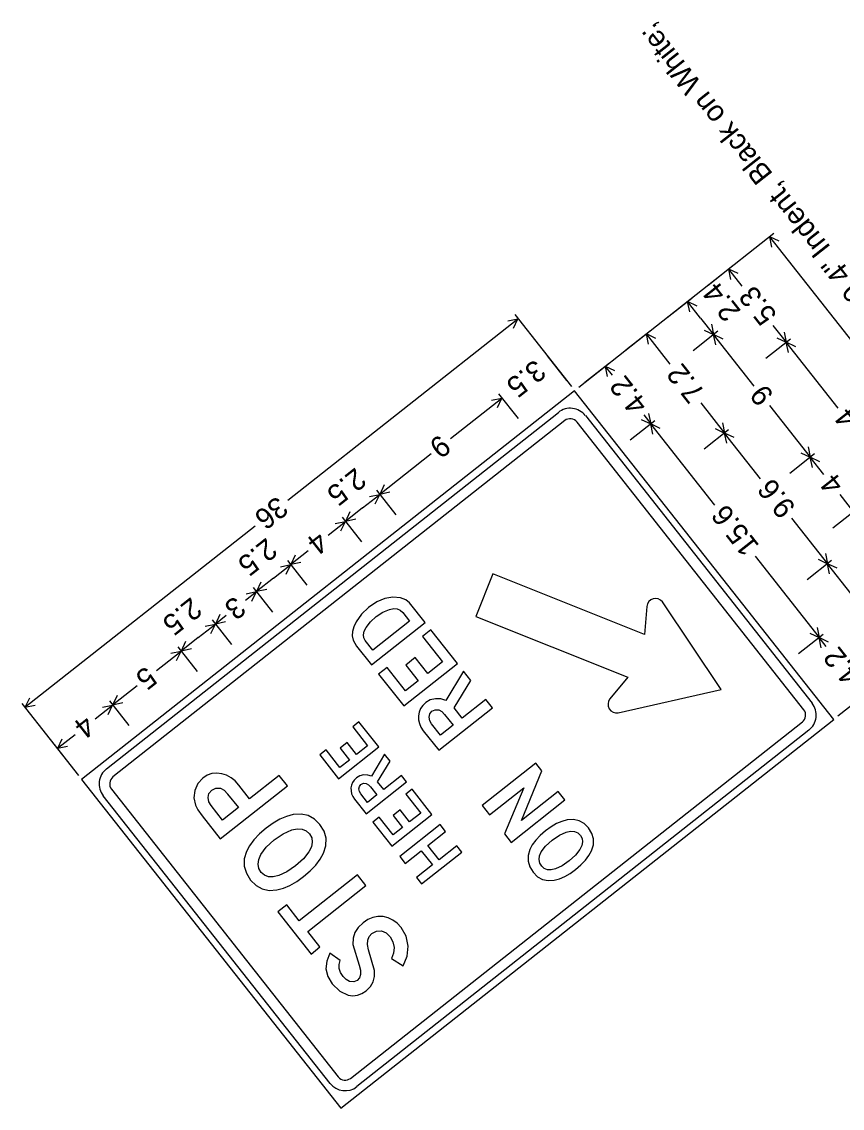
# Model space of a CAD drawing. Extents: x 672239 to 673995, y 1673540 to 1675195.
# Drawn here: x 672602.49 to 672638.35, y 1674789.09 to 1674836.55 of the extents above; entities that cross this region are included whole.
import ezdxf

# ---------------------------------------------------------------- set-up
doc = ezdxf.new("R2010")
doc.units = 0
doc.layers.add('C-ALGN-LINE', color=7, linetype='Continuous')

msp = doc.modelspace()

# ---------------------------------------------------------------- linework, layer by layer
at = {"layer": 'C-ALGN-LINE'}
for p, q in [((672635.358, 1674827.298), (672626.831, 1674820.575)), ((672640.275, 1674820.692), (672635.179, 1674827.156)), ((672635.593, 1674826.961), (672635.179, 1674827.156)), ((672635.272, 1674826.708), (672635.179, 1674827.156)), ((672633.563, 1674825.882), (672632.486, 1674825.033)), ((672633.968, 1674825), (672633.384, 1674825.741)), ((672633.797, 1674825.546), (672633.384, 1674825.741)), ((672633.476, 1674825.293), (672633.384, 1674825.741)), ((672631.768, 1674824.467), (672630.691, 1674823.618)), ((672632.156, 1674823.605), (672631.588, 1674824.326)), ((672632.002, 1674824.131), (672631.588, 1674824.326)), ((672631.681, 1674823.878), (672631.588, 1674824.326)), ((672624.033, 1674823.755), (672626.51, 1674820.613)), ((672614.118, 1674815.648), (672624.175, 1674823.575)), ((672623.727, 1674823.482), (672624.175, 1674823.575)), ((672623.98, 1674823.162), (672624.175, 1674823.575)), ((672632.156, 1674823.605), (672632.725, 1674822.884)), ((672632.632, 1674823.332), (672632.725, 1674822.884)), ((672635.318, 1674823.287), (672635.902, 1674822.546)), ((672629.973, 1674823.052), (672628.895, 1674822.203)), ((672630.83, 1674821.596), (672629.793, 1674822.91)), ((672630.207, 1674822.716), (672629.793, 1674822.91)), ((672629.886, 1674822.463), (672629.793, 1674822.91)), ((672632.904, 1674823.026), (672631.827, 1674822.176)), ((672632.904, 1674823.026), (672631.827, 1674822.176)), ((672632.311, 1674823.079), (672632.725, 1674822.884)), ((672634.502, 1674820.629), (672632.725, 1674822.884)), ((672633.138, 1674822.69), (672632.725, 1674822.884)), ((672632.817, 1674822.437), (672632.725, 1674822.884)), ((672636.082, 1674822.688), (672635.005, 1674821.838)), ((672636.082, 1674822.688), (672635.005, 1674821.838)), ((672635.488, 1674822.741), (672635.902, 1674822.546)), ((672635.809, 1674822.994), (672635.902, 1674822.546)), ((672638.171, 1674819.668), (672635.902, 1674822.546)), ((672636.316, 1674822.351), (672635.902, 1674822.546)), ((672635.995, 1674822.098), (672635.902, 1674822.546)), ((672625.448, 1674821.96), (672626.298, 1674820.883)), ((672628.177, 1674821.637), (672627.1, 1674820.788)), ((672628.306, 1674821.104), (672627.998, 1674821.495)), ((672628.412, 1674821.3), (672627.998, 1674821.495)), ((672628.091, 1674821.047), (672627.998, 1674821.495)), ((672621.226, 1674818.34), (672623.472, 1674820.111)), ((672623.024, 1674820.018), (672623.472, 1674820.111)), ((672623.277, 1674819.697), (672623.472, 1674820.111)), ((672623.331, 1674820.29), (672624.18, 1674819.213)), ((672623.331, 1674820.29), (672624.18, 1674819.213)), ((672632.167, 1674819.899), (672633.204, 1674818.584)), ((672629.671, 1674819.373), (672629.979, 1674818.982)), ((672629.886, 1674819.43), (672629.979, 1674818.982)), ((672635.171, 1674819.781), (672636.948, 1674817.527)), ((672630.159, 1674819.123), (672629.082, 1674818.274)), ((672630.159, 1674819.123), (672629.082, 1674818.274)), ((672629.566, 1674819.177), (672629.979, 1674818.982)), ((672632.781, 1674815.428), (672629.979, 1674818.982)), ((672630.393, 1674818.787), (672629.979, 1674818.982)), ((672630.072, 1674818.534), (672629.979, 1674818.982)), ((672633.111, 1674819.032), (672633.204, 1674818.584)), ((672633.383, 1674818.725), (672632.306, 1674817.876)), ((672633.383, 1674818.725), (672632.306, 1674817.876)), ((672632.79, 1674818.779), (672633.204, 1674818.584)), ((672634.776, 1674816.589), (672633.204, 1674818.584)), ((672633.618, 1674818.389), (672633.204, 1674818.584)), ((672633.297, 1674818.136), (672633.204, 1674818.584)), ((672636.856, 1674817.974), (672636.948, 1674817.527)), ((672620.379, 1674817.672), (672618.133, 1674815.902)), ((672637.128, 1674817.668), (672636.051, 1674816.819)), ((672636.535, 1674817.721), (672636.948, 1674817.527)), ((672637.548, 1674816.767), (672636.948, 1674817.527)), ((672637.362, 1674817.332), (672636.948, 1674817.527)), ((672637.041, 1674817.079), (672636.948, 1674817.527)), ((672617.992, 1674816.081), (672618.841, 1674815.004)), ((672618.328, 1674816.315), (672618.133, 1674815.902)), ((672617.385, 1674815.312), (672618.133, 1674815.902)), ((672617.685, 1674815.809), (672618.133, 1674815.902)), ((672617.938, 1674815.488), (672618.133, 1674815.902)), ((672618.581, 1674815.995), (672618.133, 1674815.902)), ((672638.237, 1674815.892), (672638.835, 1674815.133)), ((672617.385, 1674815.312), (672616.637, 1674814.722)), ((672616.832, 1674815.136), (672616.637, 1674814.722)), ((672639.015, 1674815.274), (672637.938, 1674814.425)), ((672615.877, 1674814.123), (672616.637, 1674814.722)), ((672616.189, 1674814.629), (672616.637, 1674814.722)), ((672616.442, 1674814.308), (672616.637, 1674814.722)), ((672616.496, 1674814.902), (672617.345, 1674813.825)), ((672617.085, 1674814.815), (672616.637, 1674814.722)), ((672636.132, 1674814.87), (672637.704, 1674812.875)), ((672612.688, 1674814.52), (672602.632, 1674806.592)), ((672615.004, 1674813.434), (672614.244, 1674812.835)), ((672614.439, 1674813.249), (672614.244, 1674812.835)), ((672634.537, 1674813.201), (672637.339, 1674809.647)), ((672637.611, 1674813.323), (672637.704, 1674812.875)), ((672613.496, 1674812.245), (672614.244, 1674812.835)), ((672613.796, 1674812.742), (672614.244, 1674812.835)), ((672614.049, 1674812.421), (672614.244, 1674812.835)), ((672614.102, 1674813.015), (672614.951, 1674811.938)), ((672614.691, 1674812.928), (672614.244, 1674812.835)), ((672637.884, 1674813.017), (672636.807, 1674812.168)), ((672637.291, 1674813.07), (672637.704, 1674812.875)), ((672638.741, 1674811.56), (672637.704, 1674812.875)), ((672638.118, 1674812.68), (672637.704, 1674812.875)), ((672637.797, 1674812.427), (672637.704, 1674812.875)), ((672646.68, 1674812.936), (672638.153, 1674806.213)), ((672613.496, 1674812.245), (672612.748, 1674811.656)), ((672612.606, 1674811.835), (672613.455, 1674810.758)), ((672612.942, 1674812.069), (672612.748, 1674811.656)), ((672612.272, 1674811.281), (672612.748, 1674811.656)), ((672612.3, 1674811.563), (672612.748, 1674811.656)), ((672612.553, 1674811.242), (672612.748, 1674811.656)), ((672613.195, 1674811.749), (672612.748, 1674811.656)), ((672610.811, 1674810.42), (672611.66, 1674809.343)), ((672611.147, 1674810.654), (672610.952, 1674810.241)), ((672611.428, 1674810.616), (672610.952, 1674810.241)), ((672611.4, 1674810.333), (672610.952, 1674810.241)), ((672610.204, 1674809.651), (672610.952, 1674810.241)), ((672610.505, 1674810.148), (672610.952, 1674810.241)), ((672610.757, 1674809.827), (672610.952, 1674810.241)), ((672637.246, 1674810.094), (672637.339, 1674809.647)), ((672610.204, 1674809.651), (672609.456, 1674809.061)), ((672609.651, 1674809.475), (672609.456, 1674809.061)), ((672637.518, 1674809.788), (672636.441, 1674808.939)), ((672636.925, 1674809.842), (672637.339, 1674809.647)), ((672637.647, 1674809.256), (672637.339, 1674809.647)), ((672637.752, 1674809.452), (672637.339, 1674809.647)), ((672637.432, 1674809.199), (672637.339, 1674809.647)), ((672608.386, 1674808.217), (672609.456, 1674809.061)), ((672609.009, 1674808.968), (672609.456, 1674809.061)), ((672609.261, 1674808.647), (672609.456, 1674809.061)), ((672609.315, 1674809.241), (672610.164, 1674808.164)), ((672609.904, 1674809.154), (672609.456, 1674809.061)), ((672607.534, 1674807.546), (672606.464, 1674806.702)), ((672606.659, 1674807.116), (672606.464, 1674806.702)), ((672602.491, 1674806.772), (672604.967, 1674803.63)), ((672602.827, 1674807.006), (672602.632, 1674806.592)), ((672603.08, 1674806.685), (672602.632, 1674806.592)), ((672605.693, 1674806.094), (672606.464, 1674806.702)), ((672606.017, 1674806.609), (672606.464, 1674806.702)), ((672606.269, 1674806.289), (672606.464, 1674806.702)), ((672606.323, 1674806.882), (672607.172, 1674805.805)), ((672606.912, 1674806.795), (672606.464, 1674806.702)), ((672604.819, 1674805.405), (672604.047, 1674804.797)), ((672604.242, 1674805.211), (672604.047, 1674804.797)), ((672603.906, 1674804.976), (672604.755, 1674803.899)), ((672604.495, 1674804.89), (672604.047, 1674804.797))]:
    msp.add_line(p, q, dxfattribs=at)
for points in [[(672637.974, 1674806.072), (672626.651, 1674820.434), (672605.109, 1674803.451), (672616.431, 1674789.089), (672637.974, 1674806.072), (672637.974, 1674806.072)], [(672606.195, 1674803.919), (672625.943, 1674819.487)], [(672626.226, 1674819.128), (672606.478, 1674803.56)], [(672636.668, 1674806.498), (672626.761, 1674819.064)], [(672627.12, 1674819.347), (672637.027, 1674806.781)], [(672629.712, 1674809.784), (672623.074, 1674812.433), (672622.333, 1674810.575)], [(672617.122, 1674809.279), (672617.771, 1674808.456), (672620.118, 1674810.307), (672619.439, 1674811.168), (672619.28, 1674811.298), (672619.039, 1674811.386), (672618.704, 1674811.418), (672618.358, 1674811.359), (672618.006, 1674811.208), (672617.646, 1674810.967), (672617.34, 1674810.676), (672617.099, 1674810.337), (672616.997, 1674810.12), (672616.94, 1674809.915), (672616.931, 1674809.723), (672616.968, 1674809.542), (672617.122, 1674809.279)], [(672619.142, 1674810.751), (672619.442, 1674810.37), (672617.832, 1674809.101), (672617.505, 1674809.517), (672617.441, 1674809.637), (672617.426, 1674809.774), (672617.46, 1674809.925), (672617.543, 1674810.092), (672617.731, 1674810.333), (672617.984, 1674810.564), (672618.274, 1674810.756), (672618.563, 1674810.877), (672618.746, 1674810.913), (672618.903, 1674810.904), (672619.035, 1674810.849), (672619.142, 1674810.751)], [(672629.806, 1674811.009), (672629.712, 1674809.784)], [(672633.054, 1674807.374), (672630.494, 1674811.204)], [(672622.333, 1674810.575), (672622.333, 1674810.575), (672628.97, 1674807.926)], [(672623.059, 1674806.577), (672622.769, 1674806.945), (672621.739, 1674806.133), (672621.385, 1674806.582), (672622.112, 1674807.777), (672621.79, 1674808.186), (672621.025, 1674806.904), (672620.805, 1674806.974), (672620.569, 1674806.98), (672620.343, 1674806.924), (672620.143, 1674806.808), (672620.015, 1674806.686), (672619.92, 1674806.548), (672619.858, 1674806.395), (672619.829, 1674806.227), (672619.833, 1674806.056), (672619.869, 1674805.89), (672619.938, 1674805.732), (672620.038, 1674805.58), (672620.713, 1674804.728), (672623.059, 1674806.577)], [(672628.97, 1674807.926), (672628.196, 1674806.974)], [(672628.561, 1674806.359), (672633.054, 1674807.374), (672633.054, 1674807.374)], [(672621.342, 1674805.82), (672620.789, 1674805.384), (672620.403, 1674805.874), (672620.32, 1674806.018), (672620.29, 1674806.172), (672620.319, 1674806.316), (672620.414, 1674806.432), (672620.557, 1674806.499), (672620.713, 1674806.488), (672620.851, 1674806.415), (672620.971, 1674806.29), (672621.342, 1674805.82)], [(672616.857, 1674790.395), (672636.604, 1674805.963)], [(672636.887, 1674805.604), (672617.14, 1674790.036)], [(672619.3, 1674803.344), (672619.083, 1674803.62), (672618.31, 1674803.011), (672618.045, 1674803.348), (672618.591, 1674804.244), (672618.349, 1674804.551), (672617.775, 1674803.59), (672617.61, 1674803.642), (672617.433, 1674803.647), (672617.263, 1674803.604), (672617.114, 1674803.517), (672617.018, 1674803.426), (672616.946, 1674803.322), (672616.9, 1674803.208), (672616.878, 1674803.082), (672616.881, 1674802.953), (672616.908, 1674802.829), (672616.96, 1674802.711), (672617.035, 1674802.597), (672617.541, 1674801.957), (672619.3, 1674803.344)], [(672614.103, 1674803.167), (672613.74, 1674803.627), (672612.448, 1674802.608), (672611.976, 1674803.207), (672611.813, 1674803.386), (672611.636, 1674803.529), (672611.446, 1674803.635), (672611.239, 1674803.702), (672611.016, 1674803.73), (672610.801, 1674803.708), (672610.596, 1674803.634), (672610.399, 1674803.509), (672610.185, 1674803.275), (672610.055, 1674802.975), (672610.018, 1674802.649), (672610.08, 1674802.331), (672610.184, 1674802.126), (672610.371, 1674801.866), (672611.169, 1674800.854), (672614.103, 1674803.167)], [(672618.012, 1674802.776), (672617.598, 1674802.45), (672617.309, 1674802.817), (672617.246, 1674802.925), (672617.224, 1674803.04), (672617.246, 1674803.149), (672617.316, 1674803.235), (672617.424, 1674803.286), (672617.541, 1674803.277), (672617.645, 1674803.223), (672617.734, 1674803.129), (672618.012, 1674802.776)], [(672615.963, 1674790.175), (672606.056, 1674802.742)], [(672606.415, 1674803.025), (672616.322, 1674790.458)], [(672611.957, 1674802.221), (672611.266, 1674801.677), (672610.768, 1674802.308), (672610.669, 1674802.481), (672610.633, 1674802.659), (672610.674, 1674802.839), (672610.797, 1674802.986), (672610.98, 1674803.076), (672611.17, 1674803.067), (672611.334, 1674802.979), (672611.481, 1674802.824), (672611.488, 1674802.815), (672611.957, 1674802.221)], [(672613.172, 1674801.327), (672612.876, 1674801.072), (672612.633, 1674800.815), (672612.445, 1674800.559), (672612.308, 1674800.301), (672612.216, 1674799.978), (672612.215, 1674799.662), (672612.307, 1674799.356), (672612.49, 1674799.058), (672612.73, 1674798.82), (672613.001, 1674798.669), (672613.307, 1674798.606), (672613.645, 1674798.629), (672613.926, 1674798.703), (672614.213, 1674798.824), (672614.508, 1674798.994), (672614.808, 1674799.211), (672615.1, 1674799.461), (672615.342, 1674799.714), (672615.532, 1674799.969), (672615.673, 1674800.228), (672615.78, 1674800.559), (672615.79, 1674800.88), (672615.704, 1674801.188), (672615.521, 1674801.486), (672615.283, 1674801.724), (672615.008, 1674801.874), (672614.698, 1674801.939), (672614.352, 1674801.916), (672614.066, 1674801.84), (672613.774, 1674801.716), (672613.476, 1674801.545), (672613.172, 1674801.327)], [(672625.384, 1674801.21), (672625.148, 1674801.006), (672624.954, 1674800.8), (672624.803, 1674800.595), (672624.694, 1674800.389), (672624.62, 1674800.13), (672624.619, 1674799.878), (672624.693, 1674799.633), (672624.839, 1674799.395), (672625.031, 1674799.204), (672625.248, 1674799.084), (672625.492, 1674799.033), (672625.763, 1674799.052), (672625.988, 1674799.111), (672626.217, 1674799.208), (672626.453, 1674799.343), (672626.693, 1674799.517), (672626.927, 1674799.717), (672627.12, 1674799.919), (672627.273, 1674800.124), (672627.385, 1674800.33), (672627.471, 1674800.596), (672627.479, 1674800.852), (672627.41, 1674801.098), (672627.264, 1674801.337), (672627.073, 1674801.527), (672626.854, 1674801.648), (672626.605, 1674801.699), (672626.328, 1674801.681), (672626.1, 1674801.62), (672625.866, 1674801.521), (672625.628, 1674801.384), (672625.384, 1674801.21)], [(672613.524, 1674800.81), (672613.922, 1674801.082), (672614.291, 1674801.248), (672614.533, 1674801.297), (672614.743, 1674801.283), (672614.923, 1674801.207), (672615.07, 1674801.07), (672615.164, 1674800.901), (672615.19, 1674800.716), (672615.149, 1674800.514), (672615.04, 1674800.297), (672614.798, 1674799.988), (672614.454, 1674799.678), (672614.077, 1674799.42), (672613.719, 1674799.255), (672613.479, 1674799.197), (672613.273, 1674799.2), (672613.1, 1674799.264), (672612.961, 1674799.388), (672612.859, 1674799.566), (672612.819, 1674799.757), (672612.846, 1674799.959), (672612.936, 1674800.175), (672613.172, 1674800.489), (672613.524, 1674800.81)], [(672625.666, 1674800.797), (672625.985, 1674801.014), (672626.28, 1674801.146), (672626.473, 1674801.186), (672626.641, 1674801.175), (672626.785, 1674801.114), (672626.903, 1674801.004), (672626.978, 1674800.869), (672626.999, 1674800.721), (672626.966, 1674800.56), (672626.879, 1674800.386), (672626.686, 1674800.139), (672626.41, 1674799.891), (672626.109, 1674799.684), (672625.822, 1674799.553), (672625.63, 1674799.505), (672625.465, 1674799.508), (672625.327, 1674799.559), (672625.216, 1674799.659), (672625.134, 1674799.801), (672625.102, 1674799.953), (672625.124, 1674800.116), (672625.196, 1674800.288), (672625.384, 1674800.54), (672625.666, 1674800.797)]]:
    msp.add_lwpolyline(points, dxfattribs=at)
for points in [[(672621.532, 1674808.513), (672620.375, 1674809.981), (672620.007, 1674809.691), (672620.877, 1674808.588), (672620.232, 1674808.08), (672619.684, 1674808.776), (672619.269, 1674808.449), (672619.818, 1674807.753), (672619.265, 1674807.317), (672618.456, 1674808.344), (672618.088, 1674808.054), (672619.185, 1674806.662)], [(672618.097, 1674804.87), (672617.229, 1674805.971), (672616.953, 1674805.753), (672617.606, 1674804.926), (672617.122, 1674804.545), (672616.711, 1674805.067), (672616.4, 1674804.822), (672616.812, 1674804.3), (672616.397, 1674803.973), (672615.79, 1674804.743), (672615.514, 1674804.526), (672616.337, 1674803.482)], [(672626.229, 1674802.555), (672625.939, 1674802.924), (672624.336, 1674801.66), (672625.223, 1674803.831), (672624.96, 1674804.165), (672622.613, 1674802.314), (672622.938, 1674801.902), (672624.431, 1674803.079), (672623.591, 1674801.073), (672623.881, 1674800.705)], [(672620.418, 1674801.926), (672619.55, 1674803.027), (672619.274, 1674802.809), (672619.927, 1674801.982), (672619.443, 1674801.601), (672619.032, 1674802.123), (672618.721, 1674801.878), (672619.133, 1674801.356), (672618.718, 1674801.029), (672618.111, 1674801.799), (672617.835, 1674801.581), (672618.658, 1674800.538)], [(672621.72, 1674800.274), (672621.503, 1674800.55), (672620.73, 1674799.941), (672620.24, 1674800.563), (672621.013, 1674801.172), (672620.769, 1674801.481), (672619.008, 1674800.093), (672619.252, 1674799.784), (672619.953, 1674800.336), (672620.443, 1674799.715), (672619.742, 1674799.162), (672619.96, 1674798.886)], [(672617.534, 1674798.814), (672617.166, 1674799.282), (672614.621, 1674797.276), (672614.074, 1674797.969), (672613.685, 1674797.662), (672615.132, 1674795.827), (672615.521, 1674796.134), (672614.989, 1674796.808)], [(672619.162, 1674795.317), (672619.334, 1674795.732), (672619.374, 1674796.175), (672619.285, 1674796.606), (672619.065, 1674796.991), (672618.896, 1674797.173), (672618.709, 1674797.312), (672618.505, 1674797.408), (672618.281, 1674797.459), (672618.053, 1674797.465), (672617.831, 1674797.424), (672617.616, 1674797.333), (672617.407, 1674797.196), (672617.194, 1674796.99), (672617.049, 1674796.764), (672616.973, 1674796.515), (672616.962, 1674796.246), (672617.237, 1674795.344), (672617.293, 1674795.123), (672617.297, 1674794.937), (672617.251, 1674794.788), (672617.153, 1674794.673), (672616.998, 1674794.605), (672616.818, 1674794.629), (672616.666, 1674794.712), (672616.534, 1674794.843), (672616.422, 1674795.02), (672616.363, 1674795.195), (672616.36, 1674795.367), (672616.41, 1674795.537), (672615.961, 1674795.859), (672615.817, 1674795.515), (672615.787, 1674795.179), (672615.869, 1674794.849), (672616.064, 1674794.525), (672616.393, 1674794.203), (672616.75, 1674794.029), (672616.957, 1674794.003), (672617.157, 1674794.026), (672617.353, 1674794.1), (672617.544, 1674794.224), (672617.73, 1674794.407), (672617.853, 1674794.616), (672617.913, 1674794.848), (672617.91, 1674795.107), (672617.644, 1674796.011), (672617.604, 1674796.239), (672617.614, 1674796.433), (672617.676, 1674796.593), (672617.789, 1674796.72), (672617.999, 1674796.83), (672618.213, 1674796.835), (672618.418, 1674796.747), (672618.596, 1674796.579), (672618.715, 1674796.365), (672618.762, 1674796.117), (672618.738, 1674795.862), (672618.643, 1674795.632)]]:
    msp.add_lwpolyline(points, close=True, dxfattribs=at)
for centre, radius, start, end in [((672626.461, 1674818.828), 0.838, 38.2506, 128.2508), ((672626.461, 1674818.828), 0.381, 38.2506, 128.2508), ((672630.185, 1674810.98), 0.381, 35.9748, 175.6281), ((672628.491, 1674806.734), 0.381, 140.8729, 280.5261), ((672636.368, 1674806.262), 0.838, 308.2504, 38.2506), ((672636.368, 1674806.262), 0.381, 308.2504, 38.2506), ((672606.714, 1674803.261), 0.838, 128.2505, 218.2508), ((672606.714, 1674803.261), 0.381, 128.2505, 218.2508), ((672616.621, 1674790.694), 0.381, 218.2508, 308.2504), ((672616.621, 1674790.694), 0.838, 218.2508, 308.2504)]:
    msp.add_arc(centre, radius, start, end, dxfattribs=at)

# ---------------------------------------------------------------- texts
for s, height, rotation, p in [('1.5" Radius, 0.6" Border, 0.4" Indent, Black on White; ', 0.9144, 128.2505, (672647.937, 1674813.927)), ('2.4', 0.9144, 128.2505, (672633.951, 1674823.913)), ('5.3', 0.9144, 128.2505, (672635.535, 1674823.75)), ('3.5', 0.9144, 218.2508, (672624.925, 1674821.838)), ('7.2', 0.9144, 128.2505, (672632.385, 1674820.361)), ('4.2', 0.9144, 128.2505, (672629.889, 1674819.835)), ('9', 0.914, 128.2505, (672635.388, 1674820.244)), ('13.4', 0.9144, 128.2505, (672640.136, 1674817.914)), ('9', 0.914, 218.2508, (672620.764, 1674818.558)), ('2.5', 0.9144, 218.2508, (672617.079, 1674817.108)), ('9.6', 0.9144, 128.2505, (672636.35, 1674815.332)), ('4', 0.914, 128.2505, (672638.454, 1674816.355)), ('36', 0.9144, 218.2508, (672613.656, 1674815.865)), ('15.6', 0.9144, 128.2505, (672634.754, 1674813.663)), ('4', 0.914, 218.2508, (672615.415, 1674814.341)), ('2.5', 0.9144, 218.2508, (672613.189, 1674814.041)), ('2.5', 0.9144, 218.2508, (672609.898, 1674811.447)), ('3', 0.914, 218.2508, (672611.809, 1674811.498)), ('4.2', 0.9144, 128.2505, (672639.229, 1674807.987)), ('5', 0.914, 218.2508, (672607.923, 1674808.435)), ('4', 0.914, 218.2508, (672605.23, 1674806.312))]:
    msp.add_text(s, height=height, rotation=rotation, dxfattribs=at).set_placement(p)

doc.saveas('drawing.dxf')
